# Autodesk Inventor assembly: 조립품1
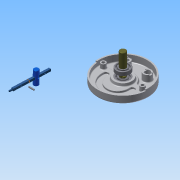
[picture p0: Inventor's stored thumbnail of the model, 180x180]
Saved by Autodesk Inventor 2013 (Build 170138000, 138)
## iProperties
Created: 2015-06
Part Number: 조립품1
Document SubType Name: Assembly
Designer: Administrator
Author: Administrator
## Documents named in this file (8)
- C:\Documents and Settings\Administrator\바탕 화면\450631V1002\조립품1.iam
- C:\Documents and Settings\Administrator\바탕 화면\450631V1002\본체.ipt
- C:\Documents and Settings\Administrator\바탕 화면\450631V1002\베어링62_22.ipt
- C:\Documents and Settings\Administrator\바탕 화면\450631V1002\축.ipt
- C:\Documents and Settings\Administrator\바탕 화면\450631V1002\멈춤링.ipt
- C:\Documents and Settings\Administrator\바탕 화면\450631V1002\평행핀.ipt
- C:\Documents and Settings\Administrator\바탕 화면\450631V1002\슬라이더.ipt
- C:\Documents and Settings\Administrator\바탕 화면\450631V1002\슬라이더2.ipt
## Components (5 placed, 3 different names)
1. KS B 2023 62/22 - 22 x 50 x 14:1
2. KS B 2023 62/22 - 22 x 50 x 14:2
3. KS B 1336 22 x 1.2:1
4. KS B 1336 22 x 1.2:2
5. KS B 1320 B B 5 x  20:1
